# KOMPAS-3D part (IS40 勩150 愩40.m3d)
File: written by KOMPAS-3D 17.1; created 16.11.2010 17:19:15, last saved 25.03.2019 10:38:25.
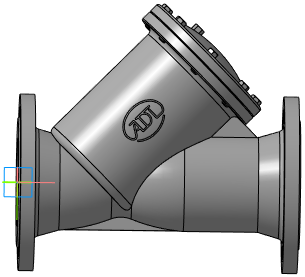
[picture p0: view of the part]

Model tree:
1. Плоскость XY
2. Плоскость ZX
3. Плоскость ZY
4. Ось X
5. Ось Y
6. Ось Z
7. Начало координат
8. Операция без истории:2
